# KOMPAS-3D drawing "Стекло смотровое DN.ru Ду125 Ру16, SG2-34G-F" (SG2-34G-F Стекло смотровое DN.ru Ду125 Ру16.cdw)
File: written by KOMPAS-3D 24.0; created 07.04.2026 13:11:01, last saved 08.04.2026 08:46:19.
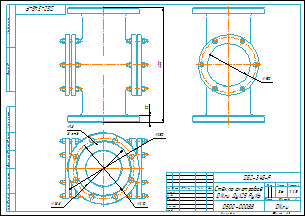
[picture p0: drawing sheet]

Document properties: Автор: Main; Форматы листов документа: A3; Полное имя файла: SG2-34G-F Стекло смотровое DN.ru Ду125 Ру16.m3d; Масса: 36; Наименование: Стекло смотровое DN.ru Ду125 Ру16; Количество листов документа: 1; Примечание: D500-00088

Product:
- Part/product: Стекло смотровое DN.ru Ду125 Ру16  | designation SG2-34G-F
    Масса: 36
    Раздел спецификации: Прочие изделия
    Примечание: D500-00088

Referenced files in D:\DN.ru Аутсерс\Стекло смотровое DN.ru\Стекло смотровое DN.ru SG2-34G-F тип В ГОСТ 21836-2021 Ду100 Ру16, углеродистая сталь, фланцевое\: SG2-34G-F тип ВСтекло смотровое DN.ru Ду100 Ру16.cdw
Referenced files in D:\DN.ru Аутсерс\Стекло смотровое DN.ru\SG2-34G-F Стекло смотровое DN.ru Ду125 Ру16\: SG2-34G-F Стекло смотровое DN.ru Ду125 Ру16.m3d
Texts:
  Стекло смотровое
  DN.ru Ду125 Ру16
  SG2-34G-F
  Стекло смотровое DN.ru Ду125 Ру16
  SG2-34G-F Стекло смотровое DN.ru Ду125 Ру16
Dimensions and other numbers on the sheet: 1:2,5; 0; 1; 2; 36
